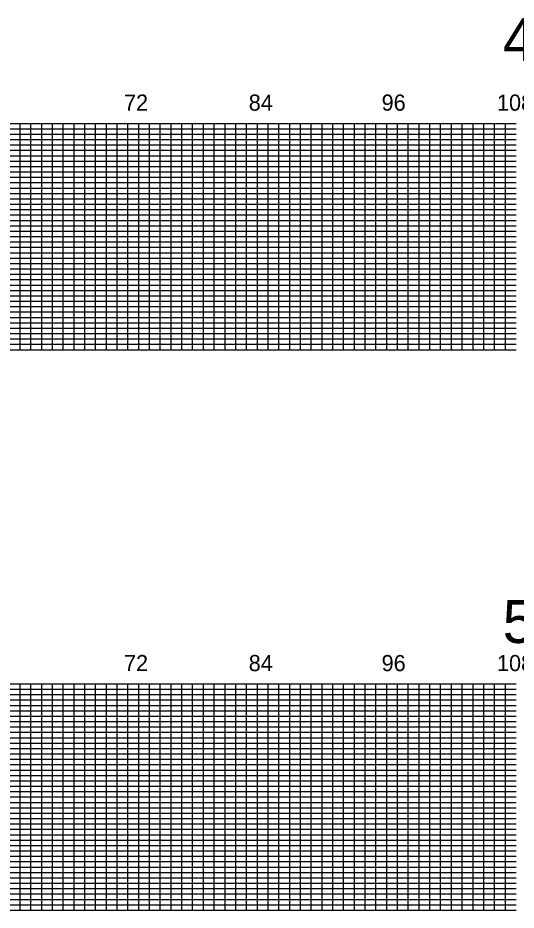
# Model space of a CAD drawing. Extents: x 1870112 to 1888282, y 758439 to 777406.
# Drawn here: x 1880621 to 1882932, y 768364 to 772503 of the extents above; entities that cross this region are included whole.
import ezdxf

# ---------------------------------------------------------------- set-up
doc = ezdxf.new("R2010")
doc.units = 0
doc.layers.add('RD_PD_WallFill', color=7, linetype='Continuous')
doc.layers.add('RD_Sketch8', color=7, linetype='Continuous')

msp = doc.modelspace()

# ---------------------------------------------------------------- linework, layer by layer
at = {"layer": 'RD_PD_WallFill'}
for p, q in [((1877581.6, 772014.1), (1882931.6, 772014.1)), ((1878031.6, 771989.1), (1882931.6, 771989.1)), ((1880631.6, 770964.1), (1880631.6, 772014.1)), ((1880681.6, 770964.1), (1880681.6, 772014.1)), ((1880731.6, 770964.1), (1880731.6, 772014.1)), ((1880781.6, 770964.1), (1880781.6, 772014.1)), ((1880831.6, 770964.1), (1880831.6, 772014.1)), ((1880881.6, 770964.1), (1880881.6, 772014.1)), ((1880931.6, 770964.1), (1880931.6, 772014.1)), ((1880981.6, 770964.1), (1880981.6, 772014.1)), ((1881031.6, 770964.1), (1881031.6, 772014.1)), ((1881081.6, 770964.1), (1881081.6, 772014.1)), ((1881131.6, 770964.1), (1881131.6, 772014.1)), ((1881181.6, 770964.1), (1881181.6, 772014.1)), ((1881231.6, 770964.1), (1881231.6, 772014.1)), ((1881281.6, 770964.1), (1881281.6, 772014.1)), ((1881331.6, 770964.1), (1881331.6, 772014.1)), ((1881381.6, 770964.1), (1881381.6, 772014.1)), ((1881431.6, 770964.1), (1881431.6, 772014.1)), ((1881481.6, 770964.1), (1881481.6, 772014.1)), ((1881531.6, 770964.1), (1881531.6, 772014.1)), ((1881581.6, 770964.1), (1881581.6, 772014.1)), ((1881631.6, 770964.1), (1881631.6, 772014.1)), ((1881681.6, 770964.1), (1881681.6, 772014.1)), ((1881731.6, 770964.1), (1881731.6, 772014.1)), ((1881781.6, 770964.1), (1881781.6, 772014.1)), ((1881831.6, 770964.1), (1881831.6, 772014.1)), ((1881881.6, 770964.1), (1881881.6, 772014.1)), ((1881931.6, 770964.1), (1881931.6, 772014.1)), ((1881981.6, 770964.1), (1881981.6, 772014.1)), ((1882031.6, 770964.1), (1882031.6, 772014.1)), ((1882081.6, 770964.1), (1882081.6, 772014.1)), ((1882131.6, 770964.1), (1882131.6, 772014.1)), ((1882181.6, 770964.1), (1882181.6, 772014.1)), ((1882231.6, 770964.1), (1882231.6, 772014.1)), ((1882281.6, 770964.1), (1882281.6, 772014.1)), ((1882331.6, 770964.1), (1882331.6, 772014.1)), ((1882381.6, 770964.1), (1882381.6, 772014.1)), ((1882431.6, 770964.1), (1882431.6, 772014.1)), ((1882481.6, 770964.1), (1882481.6, 772014.1)), ((1882531.6, 770964.1), (1882531.6, 772014.1)), ((1882581.6, 770964.1), (1882581.6, 772014.1)), ((1882631.6, 770964.1), (1882631.6, 772014.1)), ((1882681.6, 770964.2), (1882681.6, 772014.1)), ((1882731.6, 770964.1), (1882731.6, 772014.1)), ((1882781.6, 770964.1), (1882781.6, 772014.1)), ((1882831.6, 770964.1), (1882831.6, 772014.1)), ((1882881.6, 770964.1), (1882881.6, 772014.1)), ((1878031.6, 771964.1), (1882931.6, 771964.1)), ((1878031.6, 771939.1), (1882931.6, 771939.1)), ((1878031.6, 771914.1), (1882931.6, 771914.1)), ((1878031.6, 771889.1), (1882931.6, 771889.1)), ((1877581.6, 771864.1), (1882931.6, 771864.1)), ((1877581.6, 771839.1), (1882931.6, 771839.1)), ((1877581.6, 771814.1), (1882931.6, 771814.1)), ((1877581.6, 771789.1), (1882931.6, 771789.1)), ((1877581.6, 771764.1), (1882931.6, 771764.1)), ((1877581.6, 771739.1), (1882931.6, 771739.1)), ((1877581.6, 771714.1), (1882931.6, 771714.1)), ((1877581.6, 771689.1), (1882931.6, 771689.1)), ((1877581.6, 771664.1), (1882931.6, 771664.1)), ((1877581.6, 771639.1), (1882931.6, 771639.1)), ((1877581.6, 771614.1), (1882931.6, 771614.1)), ((1877581.6, 771589.1), (1882931.6, 771589.1)), ((1877581.6, 771564.1), (1882931.6, 771564.1)), ((1877581.6, 771539.1), (1882931.6, 771539.1)), ((1877581.6, 771514.1), (1882931.6, 771514.1)), ((1877581.6, 771489.1), (1882931.6, 771489.1)), ((1877581.6, 771464.1), (1882931.6, 771464.1)), ((1877581.6, 771439.1), (1882931.6, 771439.1)), ((1877581.6, 771414.1), (1882931.6, 771414.1)), ((1877581.6, 771389.1), (1882931.6, 771389.1)), ((1877581.6, 771364.1), (1882931.6, 771364.1)), ((1877581.6, 771339.1), (1882931.6, 771339.1)), ((1877581.6, 771314.1), (1882931.6, 771314.1)), ((1877581.6, 771289.1), (1882931.6, 771289.1)), ((1877581.6, 771264.1), (1882931.6, 771264.1)), ((1877581.6, 771239.1), (1882931.6, 771239.1)), ((1877581.6, 771214.1), (1882931.6, 771214.1)), ((1877581.6, 771189.1), (1882931.6, 771189.1)), ((1877581.6, 771164.1), (1882931.6, 771164.1)), ((1877581.6, 771139.1), (1882931.6, 771139.1)), ((1877581.6, 771114.1), (1882931.6, 771114.1)), ((1877581.6, 771089.1), (1882931.6, 771089.1)), ((1877581.6, 771064.1), (1882931.6, 771064.1)), ((1877581.6, 771039.1), (1882931.6, 771039.1)), ((1877581.6, 771014.1), (1882931.6, 771014.1)), ((1877581.6, 770964.1), (1882931.6, 770964.1)), ((1877631.6, 770989.1), (1882931.6, 770989.1)), ((1877581.6, 769414.1), (1882931.6, 769414.2)), ((1878031.6, 769389.1), (1882931.6, 769389.1)), ((1880631.6, 768364.2), (1880631.6, 769414.2)), ((1880681.6, 768364.1), (1880681.6, 769414.2)), ((1880731.6, 768364.2), (1880731.6, 769414.2)), ((1880781.6, 768364.2), (1880781.6, 769414.2)), ((1880831.6, 768364.2), (1880831.6, 769414.2)), ((1880881.6, 768364.2), (1880881.6, 769414.2)), ((1880931.6, 768364.2), (1880931.6, 769414.2)), ((1880981.6, 768364.1), (1880981.6, 769414.2)), ((1881031.6, 768364.1), (1881031.6, 769414.2)), ((1881081.6, 768364.2), (1881081.6, 769414.2)), ((1881131.6, 768364.2), (1881131.6, 769414.2)), ((1881181.6, 768364.2), (1881181.6, 769414.2)), ((1881231.6, 768364.2), (1881231.6, 769414.2)), ((1881281.6, 768364.2), (1881281.6, 769414.2)), ((1881331.6, 768364.2), (1881331.6, 769414.2)), ((1881381.6, 768364.2), (1881381.6, 769414.2)), ((1881431.6, 768364.2), (1881431.6, 769414.2)), ((1881481.6, 768364.2), (1881481.6, 769414.2)), ((1881531.6, 768364.2), (1881531.6, 769414.2)), ((1881581.6, 768364.2), (1881581.6, 769414.2)), ((1881631.6, 768364.2), (1881631.6, 769414.2)), ((1881681.6, 768364.2), (1881681.6, 769414.2)), ((1881731.6, 768364.2), (1881731.6, 769414.2)), ((1881781.6, 768364.2), (1881781.6, 769414.2)), ((1881831.6, 768364.2), (1881831.6, 769414.2)), ((1881881.6, 768364.2), (1881881.6, 769414.2)), ((1881931.6, 768364.2), (1881931.6, 769414.2)), ((1881981.6, 768364.2), (1881981.6, 769414.2)), ((1882031.6, 768364.2), (1882031.6, 769414.2)), ((1882081.6, 768364.2), (1882081.6, 769414.2)), ((1882131.6, 768364.2), (1882131.6, 769414.2)), ((1882181.6, 768364.2), (1882181.6, 769414.2)), ((1882231.6, 768364.2), (1882231.6, 769414.2)), ((1882281.6, 768364.2), (1882281.6, 769414.2)), ((1882331.6, 768364.2), (1882331.6, 769414.2)), ((1882381.6, 768364.2), (1882381.6, 769414.2)), ((1882431.6, 768364.2), (1882431.6, 769414.2)), ((1882481.6, 768364.2), (1882481.6, 769414.2)), ((1882531.6, 768364.2), (1882531.6, 769414.2)), ((1882581.6, 768364.2), (1882581.6, 769414.2)), ((1882631.6, 768364.2), (1882631.6, 769414.2)), ((1882681.6, 768364.2), (1882681.6, 769414.2)), ((1882731.6, 768364.2), (1882731.6, 769414.2)), ((1882781.6, 768364.2), (1882781.6, 769414.2)), ((1882831.6, 768364.2), (1882831.6, 769414.2)), ((1882881.6, 768364.2), (1882881.6, 769414.2)), ((1878031.6, 769364.1), (1882931.6, 769364.1)), ((1878031.6, 769339.1), (1882931.6, 769339.1)), ((1878031.6, 769314.2), (1882931.6, 769314.1)), ((1877581.6, 769264.1), (1882931.6, 769264.1)), ((1878031.6, 769289.1), (1882931.6, 769289.2)), ((1877581.6, 769239.1), (1882931.6, 769239.1)), ((1877581.6, 769214.1), (1882931.6, 769214.2)), ((1877581.6, 769189.2), (1882931.6, 769189.1)), ((1877581.6, 769164.2), (1882931.6, 769164.2)), ((1877581.6, 769139.1), (1882931.6, 769139.1)), ((1877581.6, 769114.1), (1882931.6, 769114.1)), ((1877581.6, 769089.2), (1882931.6, 769089.1)), ((1877581.6, 769064.1), (1882931.6, 769064.1)), ((1877581.6, 769039.2), (1882931.6, 769039.1)), ((1877581.6, 769014.1), (1882931.6, 769014.1)), ((1877581.6, 768989.1), (1882931.6, 768989.2)), ((1877581.6, 768964.1), (1882931.6, 768964.1)), ((1877581.6, 768939.1), (1882931.6, 768939.2)), ((1877581.6, 768914.1), (1882931.6, 768914.1)), ((1877581.6, 768889.1), (1882931.6, 768889.1)), ((1877581.6, 768864.2), (1882931.6, 768864.1)), ((1877581.6, 768839.1), (1882931.6, 768839.1)), ((1877581.6, 768814.1), (1882931.6, 768814.1)), ((1877581.6, 768789.1), (1882931.6, 768789.1)), ((1877581.6, 768764.1), (1882931.6, 768764.2)), ((1877581.6, 768739.1), (1882931.6, 768739.1)), ((1877581.6, 768714.1), (1882931.6, 768714.1)), ((1877581.6, 768689.1), (1882931.6, 768689.1)), ((1877581.6, 768664.1), (1882931.6, 768664.1)), ((1877581.6, 768639.1), (1882931.6, 768639.1)), ((1877581.6, 768614.1), (1882931.6, 768614.1)), ((1877581.6, 768589.1), (1882931.6, 768589.1)), ((1877581.6, 768564.1), (1882931.6, 768564.1)), ((1877581.6, 768539.1), (1882931.6, 768539.1)), ((1877581.6, 768514.1), (1882931.6, 768514.1)), ((1877581.6, 768489.1), (1882931.6, 768489.1)), ((1877581.6, 768464.1), (1882931.6, 768464.1)), ((1877581.6, 768439.1), (1882931.6, 768439.1)), ((1877581.6, 768414.1), (1882931.6, 768414.1)), ((1877631.6, 768389.1), (1882931.6, 768389.1)), ((1877581.6, 768364.1), (1882931.6, 768364.1))]:
    msp.add_line(p, q, dxfattribs=at)

# ---------------------------------------------------------------- texts
for s, p in [('72', (1881113.4, 772072.8)), ('84', (1881691.7, 772072.8)), ('96', (1882307.8, 772072.8)), ('108', (1882842.8, 772072.8)), ('72', (1881113.4, 769472.8)), ('84', (1881691.7, 769472.8)), ('96', (1882307.8, 769472.8)), ('108', (1882842.8, 769472.8))]:
    msp.add_text(s, height=75, dxfattribs=at).set_placement(p)
at = {"layer": 'RD_Sketch8'}
for s, p in [('4', (1882870.4, 772303.5)), ('5', (1882869.2, 769603.5))]:
    msp.add_text(s, height=200, dxfattribs=at).set_placement(p)

doc.saveas('drawing.dxf')
